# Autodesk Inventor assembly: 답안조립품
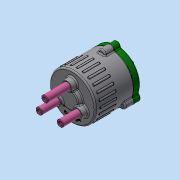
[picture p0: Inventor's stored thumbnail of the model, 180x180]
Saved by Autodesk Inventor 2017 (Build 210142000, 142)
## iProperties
Part Number: 답안조립품
Material: 일반
Document SubType Name: Assembly
Designer: MRC
Author: MRC
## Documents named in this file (15)
- C:\Users\MRC\OneDrive\바탕 화면\620811V1007\답안조립품.iam
- C:\Users\MRC\OneDrive\바탕 화면\620811V1007\본체.ipt
- C:\Users\MRC\OneDrive\바탕 화면\620811V1007\가변스프링1.ipt
- C:\Users\MRC\OneDrive\바탕 화면\620811V1007\가변스프링2.ipt
- C:\Users\MRC\OneDrive\바탕 화면\620811V1007\가변스프링3.ipt
- C:\Users\MRC\OneDrive\바탕 화면\620811V1007\개스킷.ipt
- C:\Users\MRC\OneDrive\바탕 화면\620811V1007\멈춤링 10x1.ipt
- C:\Users\MRC\OneDrive\바탕 화면\620811V1007\멈춤링 22x1.2.ipt
- C:\Users\MRC\OneDrive\바탕 화면\620811V1007\메인 축.ipt
- C:\Users\MRC\OneDrive\바탕 화면\620811V1007\베어링 NA 4900.ipt
- C:\Users\MRC\OneDrive\바탕 화면\620811V1007\볼트 M5.ipt
- C:\Users\MRC\OneDrive\바탕 화면\620811V1007\슬라이드 축.ipt
- C:\Users\MRC\OneDrive\바탕 화면\620811V1007\오일 실.ipt
- C:\Users\MRC\OneDrive\바탕 화면\620811V1007\커버.ipt
- C:\Users\MRC\OneDrive\바탕 화면\620811V1007\판캠.ipt
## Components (4 placed, 4 different names)
1. 가변스프링1:1
2. 가변스프링2:1
3. 가변스프링3:1
4. 개스킷:1
